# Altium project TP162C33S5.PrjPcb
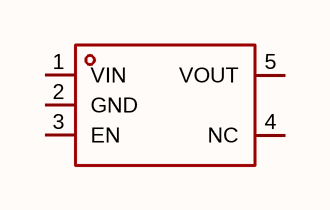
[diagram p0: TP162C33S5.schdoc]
1 sheet, 1 parts. Net scope: global (net labels, ports and power ports of the same name join across sheets).

## Sheet TP162C33S5.schdoc
size 127 x 101 mm

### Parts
U?  tp162c33s5  [SOT-23-5_L3.0-W1.7-P0.95-LS2.8-BR]  (value not drawn)

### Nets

Not connected (* = marked no-connect by the designer): U? 1(VIN) 2(GND) 3(EN) 4(NC) 5(VOUT)

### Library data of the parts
U? = tp162c33s5: 输出极性:正极;工作电压:5.5V;输出电压:3.3V;输出电流:600mA;电源纹波抑制比(PSRR):75dB@(1kHz);输出类型:固定;; Manufacturer: TECH PUBLIC(台舟); AddInBom: yes; ModelId: 0a2a1b8f50944f73965918ad6e5fe167; ModelName: SOT-23-5_L2.9-W1.6-H1.1-LS2.8-P0.95; ModelTransform: 114.173,109.636,0,180,0,0,0,0,0; Output Configuration: 正极; Voltage - Supply: 5.5V; Output Voltage: 3.3V; Output Current: 600mA; Voltage Dropout: 320mV@(600mA); standby current: 2uA; Noise: 50uVrms; Output Type: 固定; Number of Outputs: 1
